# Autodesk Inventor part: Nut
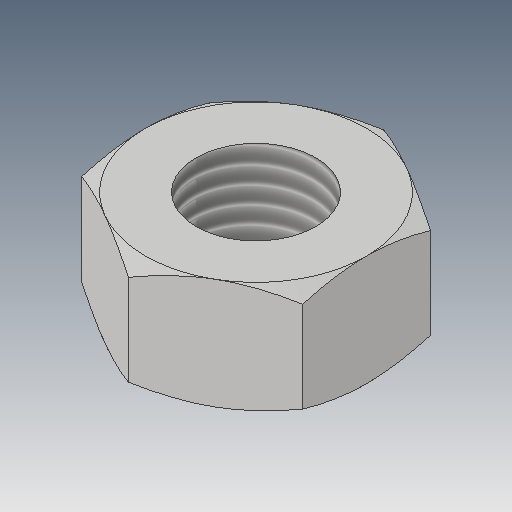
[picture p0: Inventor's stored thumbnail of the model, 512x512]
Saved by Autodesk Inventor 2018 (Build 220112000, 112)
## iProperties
Created: 2016-05
Part Number: Nut
Material: Generic
Document SubType Name: Modeling
Designer: CADCIM
Density: 1 g/cm^3
Appearance: Default
Author: CADCIM
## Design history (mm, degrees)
sketch "Sketch1"
  geometry: L1 (0, -18.475)-(-16, -9.238); L2 (-16, -9.238)-(-16, 9.238); L3 (-16, 9.238)-(0, 18.475); L4 (0, 18.475)-(16, 9.238); L5 (16, 9.238)-(16, -9.238); L6 (16, -9.238)-(0, -18.475); 2 further points
  constraints: 12 end point, 1 coincident, 13 other
  dimensions: "d0" = 32 distance between parallel lines of L2 L5
extrude "Extrusion1" new body sketch "Sketch1" distance "d1" = 16; taper "d2" = 0 deg
sketch "Sketch2"
  geometry: L1 (16, -9.238)-(16, 9.238) reference; C1 r 16 at (0, 0); 1 further point
  constraints: 1 centre point, 1 coincident, 1 tangent
extrude "Extrusion2" sketch "Sketch2" distance "d3" = 16; taper "d4" = 60 deg
sketch "Sketch3"
  geometry: L1 (0, -18.475)-(16, -9.238) reference; C1 r 16 at (0, 0); 1 further point
  constraints: 1 centre point, 1 coincident, 1 tangent
extrude "Extrusion3" sketch "Sketch3" distance "d5" = 16; taper "d6" = 60 deg
hole "Hole1" diameter "d9" = 17.294; stored, may be unused: countersink angle "d13" = 90 deg, drill point angle "d15" = 118 deg; dims "d7" = 10, "d8" = 10, "d10" = 40, "d11" = 4, "d12" = 2, "d14" = 51.2
body "Solid1"
